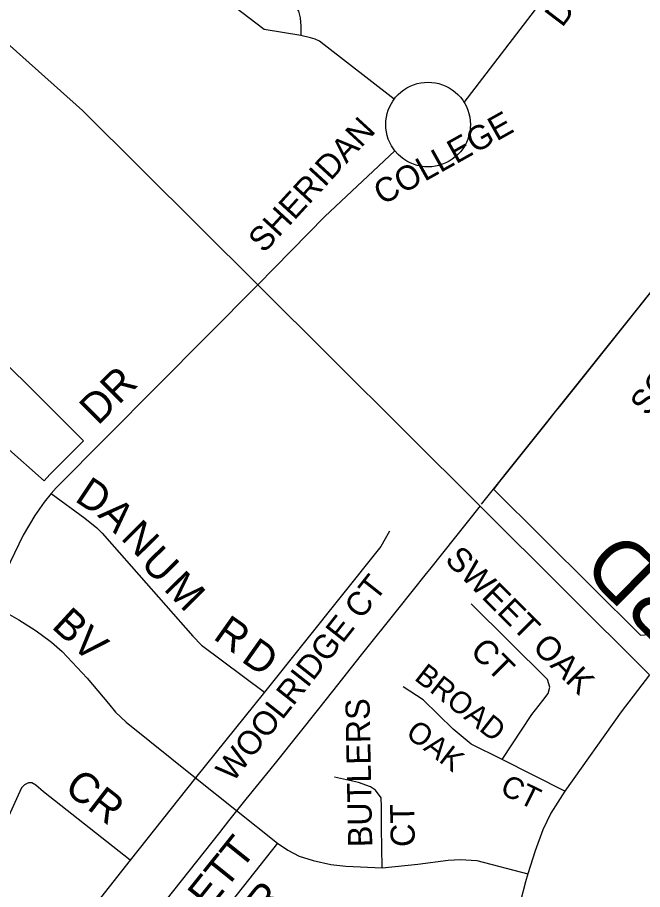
# Model space of a CAD drawing. Extents: x 586326 to 623965, y 4819854 to 4857850.
# Drawn here: x 601381 to 601899, y 4833716 to 4834438 of the extents above; entities that cross this region are included whole.
import ezdxf

# ---------------------------------------------------------------- set-up
doc = ezdxf.new("R2010")
doc.units = 0
for name, color, linetype in [('Lots_Concessions', 7, 'Continuous'), ('Major Rds and Hwys', 7, 'Continuous'), ('Major Rds Lbls', 7, 'Continuous'), ('Minor Rd Lbls', 7, 'Continuous'), ('Minor Rds', 7, 'Continuous'), ('Park Outlines', 7, 'Continuous'), ('Private Rd Lbls', 7, 'Continuous'), ('Private Rds', 7, 'Continuous'), ('Proposed Secondary Rds', 7, 'Continuous'), ('Rec Lbls', 7, 'Continuous'), ('Secondary Rds Lbls', 7, 'Continuous')]:
    doc.layers.add(name, color=color, linetype=linetype)

msp = doc.modelspace()

# ---------------------------------------------------------------- linework, layer by layer
at = {"layer": 'Lots_Concessions'}
for p, q in [((601765.96, 4834035.03), (602078.9, 4834427.32)), ((601722.99, 4833980.95), (601765.07, 4834033.7)), ((601696.57, 4833947.83), (601720.41, 4833977.72)), ((601720.41, 4833977.72), (601722.99, 4833980.95)), ((601666.6, 4833910.25), (601696.57, 4833947.83)), ((601642.63, 4833880.19), (601666.6, 4833910.25)), ((601631.03, 4833865.66), (601642.63, 4833880.19)), ((601596.25, 4833822.04), (601631.03, 4833865.66)), ((601590.45, 4833814.78), (601596.25, 4833822.04)), ((601570.96, 4833790.81), (601590.45, 4833814.78)), ((601556.62, 4833772.84), (601570.96, 4833790.81)), ((601549.19, 4833763.04), (601556.62, 4833772.84)), ((601469.96, 4833663.7), (601549.19, 4833763.04))]:
    msp.add_line(p, q, dxfattribs=at)
at = {"layer": 'Major Rds and Hwys'}
for points in [[(601580.55, 4834216.88), (601435.37, 4834361.24), (601367.65, 4834421.57)], [(601905.23, 4833893.85), (601764.81, 4834033.51), (601764.33, 4834033.99), (601580.55, 4834216.88)]]:
    msp.add_lwpolyline(points, dxfattribs=at)
at = {"layer": 'Minor Rds'}
for points in [[(601409.4, 4834043.83), (601437.19, 4834023.59), (601447.25, 4834015.56), (601451.64, 4834011.15), (601459.73, 4834001.93), (601526.59, 4833925.89), (601533.77, 4833918.22), (601586.05, 4833879.36)], [(601689.74, 4834012.76), (601682.65, 4834000.03), (601586.05, 4833879.36)], [(601782.99, 4833823.66), (601807.61, 4833860.84), (601816.77, 4833872.56), (601821.31, 4833878.37), (601822.49, 4833883.45), (601820.75, 4833889.84), (601757.4, 4833952.5)], [(601782.99, 4833823.66), (601757.37, 4833836.2), (601742.39, 4833848.82), (601717.47, 4833872.97), (601701.05, 4833883.71)], [(601586.05, 4833879.36), (601528.9, 4833808.45)], [(601835.03, 4833797.24), (601782.99, 4833823.66)], [(601528.9, 4833808.45), (601474.9, 4833740.08)], [(601683.7, 4833733.98), (601682.96, 4833767.08), (601683.19, 4833784.43), (601682.72, 4833791.94), (601678, 4833798.08), (601673.98, 4833801.06), (601663.98, 4833804.51), (601644.02, 4833809.01)], [(601474.9, 4833740.08), (601403.07, 4833796.87), (601396.6, 4833802.26), (601393.24, 4833804.38), (601390.62, 4833804.25), (601387.28, 4833802.52), (601384.76, 4833800.15), (601372.58, 4833773.44), (601358.28, 4833746.38), (601337.27, 4833711.37), (601327.89, 4833697.53), (601297.37, 4833656.23), (601269.48, 4833621.09)], [(601596.96, 4833754.27), (601534.27, 4833674.91), (601530.42, 4833668.26), (601528.37, 4833662.93), (601527.03, 4833657), (601526.66, 4833651.49), (601531.85, 4833618.67)], [(601474.9, 4833740.08), (601369.3, 4833606.41), (601364.55, 4833601.4), (601360.49, 4833598.93), (601355.15, 4833596.8), (601316.18, 4833590.13), (601308.98, 4833589.59), (601303.37, 4833590.66), (601298.84, 4833593.33), (601294.3, 4833597.06), (601269.48, 4833621.09)]]:
    msp.add_lwpolyline(points, dxfattribs=at)
at = {"layer": 'Park Outlines'}
for points in [[(601932.64, 4834244), (601845.96, 4834135.32), (601830.49, 4834115.92), (601827.37, 4834112.02), (601822.7, 4834106.16), (601819.58, 4834102.25), (601780.99, 4834053.87), (601776.32, 4834048.01), (601776, 4834047.62), (601897.84, 4833926.72), (601911.02, 4833927.61)], [(601371.85, 4834082.5), (601403.64, 4834054.5), (601408.24, 4834059.58), (601413, 4834064.51), (601435.78, 4834087.44), (601435.99, 4834087.65), (601435.78, 4834087.86), (601330.01, 4834192.96)]]:
    msp.add_lwpolyline(points, dxfattribs=at)
at = {"layer": 'Private Rds'}
for points in [[(601470.67, 4834541.28), (601479.22, 4834538.63), (601487.31, 4834534.58), (601504.65, 4834523.89), (601515.34, 4834516.09), (601526.04, 4834506.84), (601532.68, 4834500.77), (601538.46, 4834493.84), (601544.53, 4834487.77), (601550.89, 4834481.7), (601556.67, 4834476.79), (601564.76, 4834470.72), (601572.85, 4834466.09), (601599.44, 4834454.82), (601604.64, 4834452.51), (601610.42, 4834448.75), (601614.18, 4834443.55), (601615.62, 4834438.06), (601616.2, 4834431.12), (601616.2, 4834423.32)], [(601616.2, 4834423.32), (601585.82, 4834428.33), (601555.7, 4834451.37), (601525.57, 4834474.41), (601513.28, 4834483.58)], [(601751.47, 4834367.96), (601828.81, 4834468.88)], [(601693.63, 4834370.66), (601635.46, 4834415.66), (601631.67, 4834418.56), (601628.05, 4834420.36), (601624.31, 4834421.35), (601616.2, 4834423.32)], [(601693.63, 4834370.66), (601694.76, 4834372.14), (601696.83, 4834374.4), (601699.08, 4834376.46), (601701.51, 4834378.33), (601704.09, 4834379.97), (601706.81, 4834381.38), (601709.63, 4834382.55), (601712.55, 4834383.47), (601715.54, 4834384.14), (601718.57, 4834384.54), (601721.63, 4834384.67), (601724.68, 4834384.54), (601727.72, 4834384.14), (601730.7, 4834383.47), (601733.62, 4834382.55), (601736.45, 4834381.38), (601739.16, 4834379.97), (601741.74, 4834378.33), (601744.17, 4834376.46), (601746.42, 4834374.4), (601748.49, 4834372.14), (601750.35, 4834369.71), (601751.47, 4834367.96)], [(601694.21, 4834327.78), (601692.9, 4834329.48), (601691.26, 4834332.06), (601689.84, 4834334.78), (601688.67, 4834337.6), (601687.75, 4834340.52), (601687.09, 4834343.51), (601686.69, 4834346.54), (601686.56, 4834349.6), (601686.69, 4834352.66), (601687.09, 4834355.69), (601687.75, 4834358.68), (601688.67, 4834361.59), (601689.84, 4834364.42), (601691.26, 4834367.13), (601692.37, 4834368.89), (601693.63, 4834370.66)], [(601751.47, 4834367.96), (601752, 4834367.13), (601753.41, 4834364.42), (601754.58, 4834361.59), (601755.5, 4834358.68), (601756.16, 4834355.69), (601756.56, 4834352.66), (601756.7, 4834349.6), (601756.56, 4834346.54), (601756.16, 4834343.51), (601755.5, 4834340.52), (601754.58, 4834337.6), (601753.41, 4834334.78), (601752, 4834332.06), (601750.35, 4834329.48), (601748.49, 4834327.06), (601746.42, 4834324.8), (601744.17, 4834322.73), (601741.74, 4834320.87), (601739.16, 4834319.23), (601736.45, 4834317.82), (601733.62, 4834316.64), (601730.7, 4834315.72), (601727.72, 4834315.06), (601724.68, 4834314.66), (601721.63, 4834314.53), (601718.57, 4834314.66), (601715.54, 4834315.06), (601712.55, 4834315.72), (601709.63, 4834316.64), (601706.81, 4834317.82), (601704.09, 4834319.23), (601701.51, 4834320.87), (601699.08, 4834322.73), (601696.83, 4834324.8), (601694.21, 4834327.78)], [(601580.55, 4834216.88), (601636.23, 4834273.41), (601694.21, 4834327.78)]]:
    msp.add_lwpolyline(points, dxfattribs=at)
at = {"layer": 'Proposed Secondary Rds'}
for points in [[(601580.55, 4834216.88), (601413.56, 4834048.74), (601409.4, 4834043.83)], [(601409.4, 4834043.83), (601403.65, 4834036.89), (601395.84, 4834025.85), (601386.2, 4834009.54), (601375.31, 4833986.95), (601358.15, 4833951.67)], [(601358.15, 4833951.67), (601372.84, 4833944.8), (601382.45, 4833939.31), (601396.04, 4833930.8), (601401.12, 4833927.23), (601409.64, 4833920.91), (601418.56, 4833912.95), (601439.16, 4833890.84), (601456.95, 4833870.06), (601462.73, 4833862.84), (601471.42, 4833854.47), (601528.9, 4833808.45)], [(601905.23, 4833893.85), (601881.62, 4833863.05), (601835.03, 4833797.24)], [(601528.9, 4833808.45), (601596.96, 4833754.27)], [(601835.03, 4833797.24), (601823.33, 4833779.18), (601816.89, 4833765.26), (601810.3, 4833747.88), (601804.39, 4833728.95)], [(601596.96, 4833754.27), (601605.37, 4833748.51), (601614.91, 4833743.46), (601626.35, 4833740.07), (601640.97, 4833736.73), (601653.54, 4833735.32), (601683.7, 4833733.98)], [(601683.7, 4833733.98), (601713.26, 4833736.83), (601738.21, 4833740.33), (601748.16, 4833740.89), (601762.07, 4833740.01), (601804.39, 4833728.95)], [(601804.39, 4833728.95), (601802.36, 4833722.28), (601798.13, 4833706.31), (601792.74, 4833665.31)]]:
    msp.add_lwpolyline(points, dxfattribs=at)

# ---------------------------------------------------------------- texts
at = {"layer": 'Major Rds Lbls'}
msp.add_text('McLAUGHLIN RD', height=49.998, rotation=135.39929, dxfattribs=at).set_placement((602266.25, 4833637.83))
at = {"layer": 'Minor Rd Lbls'}
for s, height, rotation, p in [('D', 25, 326.30995, (601427.92, 4834038.22)), ('A', 25, 314.63967, (601447.19, 4834025.6)), ('N', 25, 314.63967, (601466.19, 4834006.6)), ('U', 25, 314.63967, (601482.52, 4833985.33)), ('SWEET OAK', 19.998, 315.00002, (601734.75, 4833988.23)), ('M', 25, 314.63967, (601501.75, 4833964.47)), ('WOOLRIDGE CT', 19.764, 51.70725, (601559.79, 4833803.95)), ('BV', 25.002, 317.42471, (601408.8, 4833933.15)), ('R', 25, 324.74366, (601542.67, 4833924.06)), ('D', 25, 324.74366, (601565.93, 4833905.39)), ('CT', 19.998, 315.00002, (601755.62, 4833912.37)), ('BROAD', 18, 321.88432, (601709.45, 4833890.16)), ('BUTLERS', 19.998, 91.10173, (601675.47, 4833751.11)), ('OAK', 18, 322.48116, (601702.18, 4833843.44)), ('CR', 25.002, 322.28404, (601419.08, 4833797.87)), ('CT', 18, 333.86902, (601780.32, 4833795.83)), ('CT', 19.998, 91.10173, (601710.77, 4833751.34)), ('SCARLETT', 25.002, 51.25405, (601470.33, 4833611.2)), ('DR', 25.002, 51.25405, (601573.53, 4833672.17))]:
    msp.add_text(s, height=height, rotation=rotation, dxfattribs=at).set_placement(p)
at = {"layer": 'Private Rd Lbls'}
for s, rotation, p in [('DRIVE', 52.84999, (601832.78, 4834429.38)), ('COLLEGE', 29.2159, (601683.79, 4834282.48)), ('SHERIDAN', 47.34605, (601585.55, 4834242.35))]:
    msp.add_text(s, height=19.998, rotation=rotation, dxfattribs=at).set_placement(p)
at = {"layer": 'Rec Lbls'}
msp.add_text("SOUTH FLETCHER'S", height=20, rotation=52.00002, dxfattribs=at).set_placement((601903.27, 4834107.29))
at = {"layer": 'Secondary Rds Lbls'}
msp.add_text('DR', height=25.002, rotation=45.14491, dxfattribs=at).set_placement((601448.26, 4834099.72))

doc.saveas('drawing.dxf')
